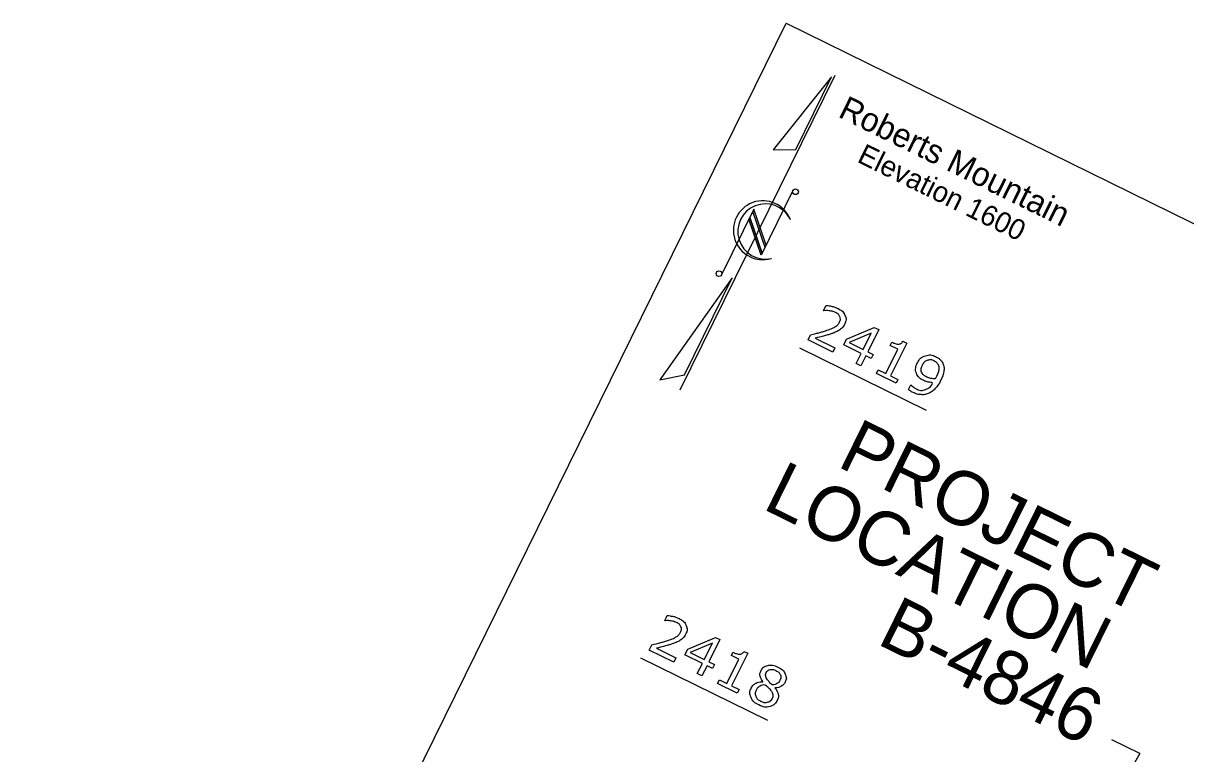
# Model space of a CAD drawing. Extents: x 1428128 to 1430390, y 857947 to 859822.
# Drawn here: x 1428344 to 1428559.3, y 859686.2 to 859821.5 of the extents above; entities that cross this region are included whole.
import ezdxf

# ---------------------------------------------------------------- set-up
doc = ezdxf.new("R2010")
doc.units = 0
for name, color, linetype in [('Old_Level_1', 7, 'Continuous'), ('Sheet North Arrow CELL', 7, 'Continuous'), ('Sheet Title CELL', 7, 'Continuous')]:
    doc.layers.add(name, color=color, linetype=linetype)

msp = doc.modelspace()

# ---------------------------------------------------------------- linework, layer by layer
at = {"layer": 'Old_Level_1'}
for p, q in [((1428487.79, 859761.44), (1428511.25, 859749.9)), ((1428458.36, 859704.02), (1428481.88, 859692.45)), ((1428550.8, 859686.28), (1428545.64, 859688.82)), ((1428550.8, 859686.28), (1428535.52, 859659.51))]:
    msp.add_line(p, q, dxfattribs=at)
for points in [[(1428492.31, 859768.28), (1428492.27, 859768.31), (1428492.74, 859769.25)], [(1428501.1, 859759.47), (1428500.1, 859759.97), (1428499.17, 859758.07), (1428498.3, 859758.5), (1428499.24, 859760.39), (1428496.01, 859761.98), (1428496.52, 859763.02), (1428501.65, 859765.21), (1428502.48, 859764.8), (1428500.46, 859760.69), (1428501.46, 859760.2), (1428501.1, 859759.47)], [(1428493.96, 859760.64), (1428489.4, 859762.88), (1428489.86, 859763.83)], [(1428490.72, 859763.2), (1428494.34, 859761.42), (1428493.96, 859760.64)], [(1428499.59, 859761.12), (1428501.09, 859764.16), (1428496.98, 859762.4), (1428499.59, 859761.12)], [(1428505.7, 859754.86), (1428502.05, 859756.65), (1428502.39, 859757.34), (1428503.79, 859756.65), (1428506.01, 859761.16), (1428504.61, 859761.85), (1428504.91, 859762.47)], [(1428506.94, 859762.63), (1428507.65, 859762.29), (1428504.66, 859756.22), (1428506.03, 859755.55), (1428505.7, 859754.86)], [(1428508.01, 859753.69), (1428508.44, 859754.56), (1428508.48, 859754.53)], [(1428462.88, 859710.86), (1428462.84, 859710.89), (1428463.31, 859711.83)], [(1428471.67, 859702.05), (1428470.67, 859702.55), (1428469.74, 859700.65), (1428468.87, 859701.08), (1428469.81, 859702.97), (1428466.58, 859704.56), (1428467.09, 859705.6), (1428472.22, 859707.79), (1428473.05, 859707.38), (1428471.03, 859703.27), (1428472.03, 859702.78), (1428471.67, 859702.05)], [(1428464.53, 859703.22), (1428459.97, 859705.46), (1428460.43, 859706.41)], [(1428461.29, 859705.78), (1428464.91, 859704), (1428464.53, 859703.22)], [(1428470.16, 859703.7), (1428471.66, 859706.74), (1428467.55, 859704.98), (1428470.16, 859703.7)], [(1428476.27, 859697.44), (1428472.62, 859699.23), (1428472.96, 859699.92), (1428474.36, 859699.23), (1428476.58, 859703.74), (1428475.18, 859704.43), (1428475.48, 859705.05)], [(1428477.51, 859705.21), (1428478.22, 859704.87), (1428475.23, 859698.8), (1428476.6, 859698.13), (1428476.27, 859697.44)], [(1428480.99, 859699.58), (1428481, 859699.61)], [(1428483.22, 859698.47), (1428483.21, 859698.44)]]:
    msp.add_lwpolyline(points, dxfattribs=at)
for points in [[(1428489.86, 859763.83), (1428490.54, 859764.01), (1428491.22, 859764.18), (1428491.9, 859764.35), (1428492.51, 859764.55), (1428493.79, 859764.96), (1428494.35, 859765.3), (1428494.92, 859765.63), (1428495.2, 859766.21), (1428495.46, 859766.73), (1428495.26, 859767.2), (1428495.06, 859767.66), (1428494.44, 859767.97), (1428494.02, 859768.17), (1428493.47, 859768.26), (1428492.92, 859768.36), (1428492.31, 859768.28)], [(1428492.74, 859769.25), (1428493.13, 859769.25), (1428493.74, 859769.12), (1428494.34, 859768.99), (1428494.84, 859768.74), (1428495.87, 859768.23), (1428496.22, 859767.44), (1428496.56, 859766.65), (1428496.14, 859765.8), (1428495.95, 859765.42), (1428495.69, 859765.13), (1428495.43, 859764.85), (1428495.09, 859764.64), (1428494.78, 859764.45), (1428494.41, 859764.3), (1428494.04, 859764.14), (1428493.54, 859763.98), (1428492.82, 859763.74), (1428492.08, 859763.55), (1428491.35, 859763.36), (1428490.72, 859763.2)], [(1428504.91, 859762.47), (1428505.2, 859762.33), (1428505.55, 859762.21), (1428505.9, 859762.1), (1428506.11, 859762.11), (1428506.37, 859762.12), (1428506.58, 859762.23), (1428506.78, 859762.35), (1428506.94, 859762.63)], [(1428508.48, 859754.53), (1428508.58, 859754.4), (1428508.79, 859754.22), (1428509, 859754.04), (1428509.29, 859753.9), (1428510.29, 859753.41), (1428511.15, 859753.73), (1428512.01, 859754.05), (1428512.62, 859755.06), (1428512.07, 859755.01), (1428511.65, 859755.08), (1428511.23, 859755.16), (1428510.79, 859755.37), (1428510.37, 859755.58), (1428510.08, 859755.82), (1428509.78, 859756.07), (1428509.56, 859756.47), (1428509.3, 859756.94), (1428509.31, 859757.47), (1428509.32, 859757.99), (1428509.61, 859758.58), (1428510.11, 859759.62), (1428511.11, 859759.93), (1428512.11, 859760.24), (1428513.08, 859759.76), (1428513.57, 859759.52), (1428513.91, 859759.17), (1428514.25, 859758.81), (1428514.42, 859758.35), (1428514.62, 859757.79), (1428514.53, 859757.1), (1428514.45, 859756.4), (1428513.99, 859755.47)], [(1428513.17, 859756.12), (1428513.51, 859756.82), (1428513.58, 859757.31), (1428513.64, 859757.81), (1428513.51, 859758.17), (1428513.39, 859758.48), (1428513.19, 859758.68), (1428512.99, 859758.89), (1428512.71, 859759.03), (1428512.06, 859759.35), (1428511.48, 859759.13), (1428510.91, 859758.91), (1428510.54, 859758.17), (1428510.33, 859757.74), (1428510.32, 859757.41), (1428510.31, 859757.08), (1428510.5, 859756.73), (1428510.63, 859756.49), (1428510.85, 859756.33), (1428511.07, 859756.16), (1428511.37, 859756.01), (1428511.72, 859755.84), (1428512.13, 859755.76), (1428512.54, 859755.67), (1428512.94, 859755.7), (1428512.99, 859755.79), (1428513.05, 859755.88), (1428513.1, 859755.97), (1428513.17, 859756.12)], [(1428513.99, 859755.47), (1428513.56, 859754.58), (1428513, 859753.96), (1428512.44, 859753.34), (1428511.79, 859753.04), (1428511.12, 859752.72), (1428510.37, 859752.75), (1428509.61, 859752.77), (1428508.77, 859753.18), (1428508.54, 859753.3), (1428508.34, 859753.43), (1428508.15, 859753.55), (1428508.01, 859753.69)], [(1428463.31, 859711.83), (1428463.7, 859711.83), (1428464.31, 859711.7), (1428464.91, 859711.57), (1428465.41, 859711.32), (1428466.44, 859710.81), (1428466.79, 859710.02), (1428467.13, 859709.23), (1428466.71, 859708.38), (1428466.52, 859708), (1428466.26, 859707.71), (1428466, 859707.43), (1428465.66, 859707.22), (1428465.35, 859707.03), (1428464.98, 859706.88), (1428464.61, 859706.72), (1428464.11, 859706.56), (1428463.39, 859706.32), (1428462.65, 859706.13), (1428461.92, 859705.94), (1428461.29, 859705.78)], [(1428460.43, 859706.41), (1428461.11, 859706.59), (1428461.79, 859706.76), (1428462.47, 859706.93), (1428463.08, 859707.13), (1428464.36, 859707.54), (1428464.92, 859707.88), (1428465.49, 859708.21), (1428465.77, 859708.79), (1428466.03, 859709.31), (1428465.83, 859709.78), (1428465.63, 859710.24), (1428465.01, 859710.55), (1428464.59, 859710.75), (1428464.04, 859710.84), (1428463.49, 859710.94), (1428462.88, 859710.86)], [(1428475.48, 859705.05), (1428475.77, 859704.91), (1428476.12, 859704.79), (1428476.47, 859704.68), (1428476.68, 859704.69), (1428476.94, 859704.7), (1428477.15, 859704.81), (1428477.35, 859704.93), (1428477.51, 859705.21)], [(1428481, 859699.61), (1428480.6, 859700.16), (1428480.51, 859700.63), (1428480.42, 859701.11), (1428480.68, 859701.62), (1428481.05, 859702.38), (1428481.92, 859702.58), (1428482.79, 859702.78), (1428483.76, 859702.3), (1428484.77, 859701.81), (1428485.13, 859701.03), (1428485.49, 859700.25), (1428485.13, 859699.5), (1428484.9, 859699.05), (1428484.4, 859698.75), (1428483.9, 859698.45), (1428483.22, 859698.47)], [(1428484.23, 859699.93), (1428484.47, 859700.42), (1428484.24, 859700.89), (1428484.01, 859701.36), (1428483.43, 859701.64), (1428482.86, 859701.92), (1428482.36, 859701.83), (1428481.86, 859701.74), (1428481.63, 859701.28), (1428481.47, 859700.95), (1428481.54, 859700.63), (1428481.61, 859700.3), (1428481.89, 859699.93), (1428482.01, 859699.77), (1428482.26, 859699.48), (1428482.51, 859699.2), (1428482.77, 859698.96), (1428483.36, 859699.04), (1428483.69, 859699.28), (1428484.02, 859699.51), (1428484.23, 859699.93)], [(1428483.69, 859696.12), (1428483.26, 859695.25), (1428482.29, 859695), (1428481.33, 859694.76), (1428480.3, 859695.27), (1428479.2, 859695.81), (1428478.83, 859696.69), (1428478.46, 859697.57), (1428478.89, 859698.46), (1428479.17, 859699.02), (1428479.72, 859699.31), (1428480.27, 859699.6), (1428480.99, 859699.58)], [(1428482.72, 859696.49), (1428482.92, 859696.91), (1428482.86, 859697.25), (1428482.8, 859697.59), (1428482.39, 859698.1), (1428482.23, 859698.31), (1428482.02, 859698.52), (1428481.8, 859698.73), (1428481.46, 859699.09), (1428480.94, 859699.07), (1428480.51, 859698.81), (1428480.08, 859698.55), (1428479.84, 859698.07), (1428479.54, 859697.46), (1428479.77, 859696.86), (1428479.99, 859696.26), (1428480.64, 859695.94), (1428481.3, 859695.61), (1428481.86, 859695.76), (1428482.43, 859695.9), (1428482.72, 859696.49)], [(1428483.21, 859698.44), (1428483.71, 859697.86), (1428483.85, 859697.3), (1428483.99, 859696.73), (1428483.69, 859696.12)]]:
    msp.add_open_spline(points, degree=3, dxfattribs=at)
at = {"layer": 'Sheet North Arrow CELL'}
for p, q in [((1428465.68, 859753.62), (1428494.38, 859811.94)), ((1428486.59, 859790.56), (1428480.7, 859778.59)), ((1428479.36, 859787.11), (1428473.37, 859774.95)), ((1428481.62, 859780.46), (1428479.36, 859787.11)), ((1428480.7, 859778.59), (1428478.44, 859785.25)), ((1428479.14, 859786.67), (1428478.6, 859785.58)), ((1428480.87, 859778.92), (1428478.6, 859785.58)), ((1428478.6, 859785.58), (1428480.87, 859778.92)), ((1428481.41, 859780.02), (1428479.14, 859786.67)), ((1428486.05, 859785.29), (1428486.09, 859785.21)), ((1428480.87, 859778.92), (1428481.41, 859780.02))]:
    msp.add_line(p, q, dxfattribs=at)
for points in [[(1428493.73, 859811.63), (1428482.95, 859798.12), (1428487.1, 859798.17)], [(1428475.32, 859774.4), (1428461.91, 859755.48), (1428466.49, 859756.45)]]:
    msp.add_lwpolyline(points, close=True, dxfattribs=at)
for centre in [(1428487.06, 859790.32), (1428472.89, 859775.16)]:
    msp.add_circle(centre, 0.53, dxfattribs=at)
for centre, radius, start, end in [((1428481.01, 859783.2), 5.46, 21.6401, 286.1942), ((1428481.49, 859782.97), 5.12, 26.8952, 282.4288)]:
    msp.add_arc(centre, radius, start, end, dxfattribs=at)
at = {"layer": 'Sheet Title CELL'}
for p, q in [((1428344.05, 859534.41), (1428485.33, 859821.53)), ((1428485.33, 859821.53), (1428763.48, 859684.67))]:
    msp.add_line(p, q, dxfattribs=at)

# ---------------------------------------------------------------- texts
at = {"layer": 'Old_Level_1'}
for s, height, p in [('Roberts Mountain', 4.4, (1428494.76, 859804.28)), ('Elevation 1600', 3.8, (1428498.27, 859795.94)), ('PROJECT', 10, (1428494.51, 859739.57)), ('LOCATION', 10, (1428480.7, 859731.74)), ('B-4846', 10, (1428501.88, 859706.71))]:
    msp.add_text(s, height=height, rotation=333.8001, dxfattribs=at).set_placement(p)

doc.saveas('drawing.dxf')
